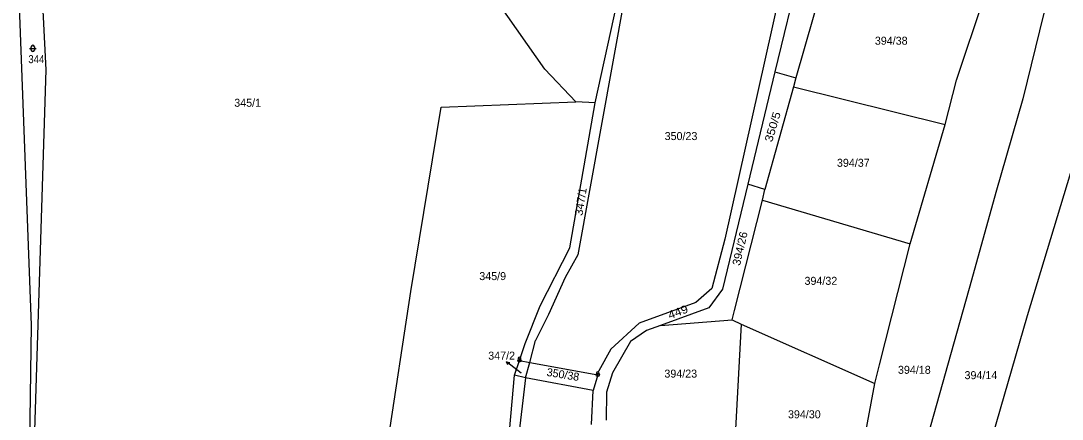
# Model space of a CAD drawing. Extents: x -680102 to -677253, y -1007548 to -1006096.
# Drawn here: x -678281.3 to -677956, y -1006809.8 to -1006685.2 of the extents above; entities that cross this region are included whole.
import ezdxf
from ezdxf.enums import TextEntityAlignment as Align

# ---------------------------------------------------------------- set-up
doc = ezdxf.new("R2010")
doc.units = 0
for name, color, linetype, lineweight in [('1', 7, 'Continuous', 25), ('16', 7, 'Continuous', 25), ('24', 7, 'Continuous', 25), ('25', 7, 'Continuous', 25)]:
    doc.layers.add(name, color=color, linetype=linetype, lineweight=lineweight)
doc.layers.add('18', color=7, linetype='Continuous')

msp = doc.modelspace()

# ---------------------------------------------------------------- linework, layer by layer
at = {"layer": '1'}
for p, q in [((-678284.39, -1006611.4), (-678278.02, -1006780.4)), ((-678041.86, -1006666.11), (-678061.39, -1006753.42)), ((-677989.01, -1006703.77), (-677979.06, -1006673.97)), ((-678092.6, -1006677.21), (-678107.32, -1006758.39)), ((-678107.98, -1006710.54), (-678117.66, -1006700.24)), ((-678045.75, -1006701.17), (-678039.17, -1006702.97)), ((-678039.96, -1006705.81), (-677992.57, -1006717.58)), ((-677992.57, -1006717.58), (-677989.01, -1006703.77)), ((-678159.5, -1006769.81), (-678150.03, -1006712.18)), ((-678150.03, -1006712.18), (-678107.98, -1006710.54)), ((-678101.85, -1006710.81), (-678107.98, -1006710.54)), ((-678003.54, -1006754.96), (-677992.57, -1006717.58)), ((-678054.2, -1006736.3), (-678062.09, -1006769.14)), ((-678048.93, -1006737.91), (-678054.2, -1006736.3)), ((-678049.66, -1006741.28), (-678003.54, -1006754.96)), ((-678013.09, -1006792.81), (-678003.54, -1006754.96)), ((-678107.32, -1006758.39), (-678111.24, -1006765.48)), ((-678111.24, -1006765.48), (-678116.5, -1006777.07)), ((-678170.61, -1006843.05), (-678159.5, -1006769.81)), ((-678062.09, -1006769.14), (-678066.42, -1006774.93)), ((-678070.48, -1006773.28), (-678088.12, -1006779.72)), ((-678116.5, -1006777.07), (-678120.54, -1006785.15)), ((-678059.07, -1006778.74), (-678058.34, -1006775.81)), ((-678278.02, -1006780.4), (-678278.66, -1006825.88)), ((-678088.12, -1006779.72), (-678097, -1006787.89)), ((-678081.52, -1006780.45), (-678059.07, -1006778.74)), ((-678059.07, -1006778.74), (-678056.3, -1006780.08)), ((-678056.3, -1006780.08), (-678058.07, -1006812.87)), ((-678056.3, -1006780.08), (-678014.55, -1006798.57)), ((-678097, -1006787.89), (-678100.7, -1006794.67)), ((-678014.55, -1006798.57), (-678013.09, -1006792.81)), ((-678130.28, -1006832.34), (-678127.05, -1006795.99)), ((-678123.63, -1006796.85), (-678128.76, -1006840.48)), ((-678123.63, -1006796.85), (-678127.05, -1006795.99)), ((-678102.52, -1006800.76), (-678123.63, -1006796.85)), ((-678101.08, -1006795.94), (-678102.52, -1006800.76)), ((-678102.99, -1006811.44), (-678102.52, -1006800.76)), ((-678098.32, -1006801.33), (-678098.43, -1006810.04))]:
    msp.add_line(p, q, dxfattribs=at)
for points in [[(-678273.4, -1006700.49), (-678275.33, -1006661.29), (-678279.05, -1006585.61)], [(-678101.85, -1006710.81), (-678096.1, -1006684.25), (-678090.29, -1006657.44), (-678090.32, -1006645.06), (-678090.33, -1006642.05)], [(-678026.83, -1006659.74), (-678028.18, -1006664.46), (-678039.17, -1006702.97)], [(-678117.66, -1006700.24), (-678131.87, -1006679.97), (-678146.27, -1006668.81)], [(-678038, -1006668.86), (-678045.75, -1006701.17), (-678054.2, -1006736.3)], [(-677961.73, -1006682.75), (-677968.34, -1006709.62), (-677976.77, -1006738.82), (-677984.36, -1006766.34), (-678000.82, -1006824.88), (-678012.04, -1006873.51), (-678018.16, -1006910.34), (-678018.27, -1006918.46)], [(-677966.9, -1006777.33), (-677939.1, -1006685.51), (-677938.25, -1006682.71)], [(-678278.66, -1006825.88), (-678277.36, -1006826.65), (-678273.4, -1006700.49)], [(-678039.17, -1006702.97), (-678039.96, -1006705.81), (-678048.93, -1006737.91)], [(-678123.78, -1006786.11), (-678119.07, -1006774.33), (-678109.82, -1006756.15), (-678101.85, -1006710.81)], [(-678058.34, -1006775.81), (-678049.66, -1006741.28), (-678048.93, -1006737.91)], [(-678061.39, -1006753.42), (-678065.42, -1006768.86), (-678070.48, -1006773.28)], [(-678066.42, -1006774.93), (-678081.52, -1006780.45), (-678085.81, -1006782.02)], [(-677988.6, -1006862.09), (-677978.95, -1006819.11), (-677966.9, -1006777.33)], [(-678085.81, -1006782.02), (-678090.82, -1006785.52), (-678096.52, -1006795.31), (-678098.32, -1006801.33)], [(-678127.05, -1006795.99), (-678125.53, -1006791.4), (-678123.78, -1006786.11)], [(-678123.63, -1006796.85), (-678122.35, -1006792), (-678120.54, -1006785.15)], [(-678125.53, -1006791.4), (-678122.35, -1006792), (-678101.08, -1006795.94), (-678100.7, -1006794.67)], [(-678018.67, -1006821.09), (-678017.94, -1006817.12), (-678014.55, -1006798.57)]]:
    msp.add_lwpolyline(points, dxfattribs=at)
at = {"layer": '16'}
for p, q in [((-678127.25, -1006793.65), (-678129.617, -1006791.808)), ((-678124.96, -1006795.42), (-678127.25, -1006793.65))]:
    msp.add_line(p, q, dxfattribs=at)
msp.add_lwpolyline([(-678129.135, -1006792.816), (-678129.617, -1006791.808), (-678128.521, -1006792.027)], dxfattribs=at)
at = {"layer": '24'}
for centre, radius in [((-678125.53, -1006791.4), 0.5), ((-678125.53, -1006791.4), 0.022), ((-678101.08, -1006795.94), 0.5), ((-678101.08, -1006795.94), 0.022)]:
    msp.add_circle(centre, radius, dxfattribs=at)
for centre in [(-678125.531, -1006790.837), (-678101.081, -1006795.377)]:
    msp.add_arc(centre, 0.437, 328.35109, 209.97456, dxfattribs=at)
at = {"layer": '25'}
for p, q in [((-678278.54, -1006693.81), (-678276.54, -1006693.81)), ((-678278.04, -1006694.31), (-678278.04, -1006693.31)), ((-678277.04, -1006693.31), (-678277.04, -1006694.31))]:
    msp.add_line(p, q, dxfattribs=at)
for centre, start, end in [((-678277.54, -1006693.31), 0.101, 180.00143), ((-678277.54, -1006694.31), 180.10243, 0.00286)]:
    msp.add_arc(centre, 0.5, start, end, dxfattribs=at)

# ---------------------------------------------------------------- texts
at = {"layer": '16'}
msp.add_text('347/2', height=2.5, dxfattribs=at).set_placement((-678131.11, -1006791.15), align=Align.CENTER)
at = {"layer": '18'}
for s, p in [('394/38', (-678014.53, -1006692.64)), ('345/1', (-678214.63, -1006712.05)), ('350/23', (-678080.19, -1006722.47)), ('394/37', (-678026.37, -1006730.83)), ('345/9', (-678138.09, -1006766.27)), ('394/32', (-678036.5, -1006767.75)), ('394/18', (-678007.31, -1006795.59)), ('394/23', (-678080.27, -1006796.77)), ('394/14', (-677986.52, -1006797.26)), ('394/30', (-678041.67, -1006809.5))]:
    msp.add_text(s, height=2.5, dxfattribs=at).set_placement(p)
at = {"layer": '18', "width": 0.9}
msp.add_text('344', height=2.5, dxfattribs=at).set_placement((-678278.96, -1006698.41))
at = {"layer": '18'}
for s, rotation, width, p in [('350/5', 73.201, 1.15, (-678046.643, -1006723.291)), ('394/26', 77.001, 1.05, (-678056.659, -1006761.911)), ('449', 20.8, 1.15, (-678078.595, -1006778.553))]:
    msp.add_text(s, height=2.5, rotation=rotation, dxfattribs=dict(at, width=width)).set_placement(p)
at = {"layer": '18', "width": 1.05}
msp.add_text('347/1', height=2.5, rotation=81.001, dxfattribs=at).set_placement((-678105.184, -1006741.914), align=Align.CENTER)
at = {"layer": '18'}
msp.add_text('350/38', height=2.5, rotation=350.803, dxfattribs=at).set_placement((-678112.136, -1006797.029), align=Align.CENTER)
msp.add_text('347/2', height=0.1, dxfattribs=at).set_placement((-678124.76, -1006795.22), align=Align.CENTER)

doc.saveas('drawing.dxf')
